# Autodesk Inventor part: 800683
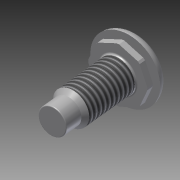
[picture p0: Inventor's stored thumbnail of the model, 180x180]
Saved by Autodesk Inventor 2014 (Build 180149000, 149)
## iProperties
Created: 2007-10
Part Number: 800683
Document SubType Name: Modeling
Designer: JJ
Density: 7.86 g/cm^3
Mass: 20.0028 g
Surface Area: 15.6834 cm^2
Volume: 2.54489 cm^3
Material: Steel, Mild
Description: DR342 M12 X 14
Appearance: Steel
Component Category: Fasteners
Author: JJ
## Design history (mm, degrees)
workplane "Work Plane1"
sketch "Sketch1"
  geometry: L1 (-510.383, -1.79)-(-510.383, 8.99) reference; L2 (-5.39, 2661.665)-(5.39, 2661.665) reference; L3 (-510.382, 8.99)-(-510.382, -1.79) reference; C1 r 3.85 at (0, 3.6)
  constraints: 1 centre point
  dimensions: "d0" = 7.7 diameter of C1; "d1" = 510.38254 distance from line of L1 C1.centre; "d2" = 2658.06461 distance from line of L2 C1.centre
extrude "Extrusion1" new body sketch "Sketch1" distance "d3" = 5; taper "d4" = 0 deg
sketch "Sketch2"
  geometry: C1 r 3.85 at (0, 0) reference; C2 r 4.946 at (0, 0)
  constraints: 1 centre point, 1 coincident
  dimensions: "d5" = 9.89173 diameter of C2
extrude "Extrusion2" join sketch "Sketch2" distance "d6" = 17; taper "d7" = 0 deg
sketch "Sketch3"
  geometry: L1 (0, -8.199)-(-5.798, -5.798); L2 (-5.798, -5.798)-(-8.199, 0); L3 (-8.199, 0)-(-5.798, 5.798); L4 (-5.798, 5.798)-(0, 8.199); L5 (0, 8.199)-(5.798, 5.798); L6 (5.798, 5.798)-(8.199, 0); L7 (8.199, 0)-(5.798, -5.798); L8 (5.798, -5.798)-(0, -8.199); L9 (-11.927, -510.383)-(14.166, -510.383) reference; L10 (2658.065, -11.479)-(2658.065, 11.479) reference; L11 (14.166, -510.382)-(-11.927, -510.382) reference; C1 r 4.946 at (0, 0) reference; 1 further point
  constraints: 16 end point, 1 coincident, 17 other
  dimensions: "d8" = 5.79765 horizontal distance of L1.start L1.end; "d9" = 2.40146 vertical distance of L1.start L1.end
extrude "Extrusion3" join sketch "Sketch3" distance "d10" = 1.8; taper "d11" = 0 deg
sketch "Sketch4"
  geometry: L1 (-12.189, -510.383)-(14.428, -510.383) reference; L2 (2658.065, -11.479)-(2658.065, 11.479) reference; L3 (14.428, -510.382)-(-12.189, -510.382) reference; C1 r 6.321 at (0, 0)
  constraints: 1 centre point
  dimensions: "d12" = 12.64212 diameter of C1; "d14" = 510.38235 distance from line of L3 C1.centre; "d15" = 2658.06461 distance from line of L2 C1.centre
extrude "Extrusion4" join sketch "Sketch4" distance "d16" = 0.7; taper "d17" = 0 deg
sketch "Sketch5"
  geometry: C1 r 6.321 at (0, 0) reference; C2 r 9.5 at (0, 0)
  constraints: 1 centre point, 1 coincident
  dimensions: "d18" = 19 diameter of C2
extrude "Extrusion5" join sketch "Sketch5" distance "d19" = 3; taper "d20" = 0 deg
fillet "Fillet1" dims "d21" = 3, "d22" = 1, "d23" = 0.5, "d24" = 0.25
sketch "Sketch6"
  geometry: C1 r 6.5 at (0, 0) reference; C2 r 5 at (0, 0)
  constraints: 1 centre point, 1 coincident
  dimensions: "d25" = 10 diameter of C2
extrude "Extrusion6" cut sketch "Sketch6" distance "d26" = 2; taper "d27" = 0 deg
fillet "Fillet2" dims "d28" = 0.5
chamfer "Chamfer2" distance "d32" = 0.37662; stored, may be unused: second distance "d33" = 2, angle "d34" = 45 deg
chamfer "Chamfer3" distance "d35" = 0.37662; stored, may be unused: second distance "d36" = 2, angle "d37" = 45 deg
chamfer "Chamfer4" distance "d38" = 0.37662; stored, may be unused: second distance "d39" = 2, angle "d40" = 45 deg
chamfer "Chamfer5" distance "d41" = 0.37662; stored, may be unused: second distance "d42" = 2, angle "d43" = 45 deg
chamfer "Chamfer6" distance "d44" = 0.37662; stored, may be unused: second distance "d45" = 2, angle "d46" = 45 deg
chamfer "Chamfer7" distance "d47" = 0.37662; stored, may be unused: second distance "d48" = 2, angle "d49" = 45 deg
chamfer "Chamfer8" distance "d50" = 0.37662; stored, may be unused: second distance "d51" = 2, angle "d52" = 45 deg
chamfer "Chamfer9" distance "d53" = 0.37662; stored, may be unused: second distance "d54" = 2, angle "d55" = 45 deg
workplane "Work Plane3"
  workplane "Work Plane2"
chamfer "Chamfer10" distance "d58" = 1.095; stored, may be unused: second distance "d59" = 1.298, angle "d60" = 45 deg
thread "Thread1" dims "d61" = 10, "d62" = 0
body "Solid1"
other parameters: "d56" = 90 deg, "d57" = -7.57499
